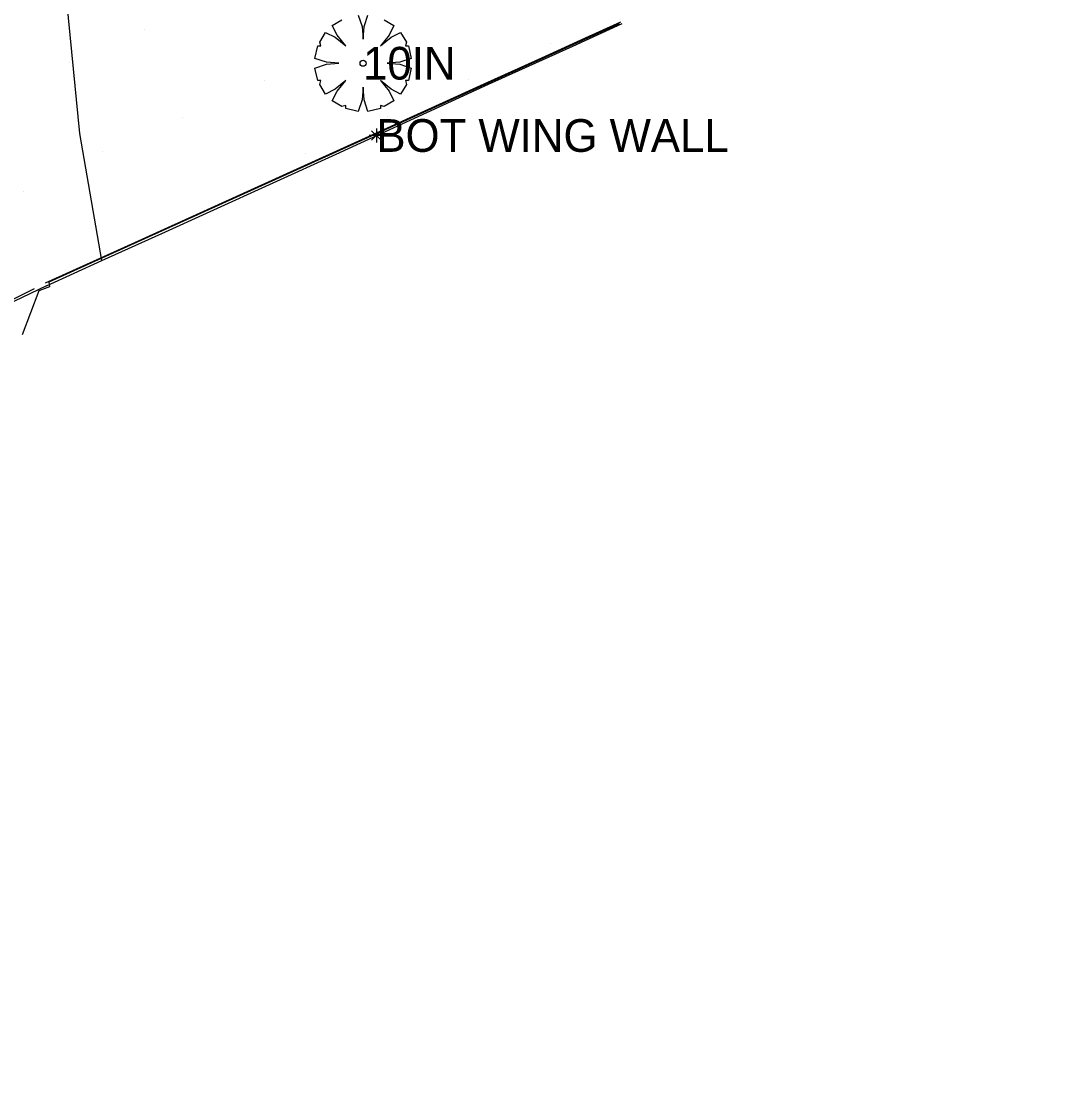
# Model space of a CAD drawing. Extents: x 1729983 to 1730242, y 468641 to 469019.
# Drawn here: x 1730180.1 to 1730237.3, y 468820 to 468879.2 of the extents above; entities that cross this region are included whole.
import ezdxf

# ---------------------------------------------------------------- set-up
doc = ezdxf.new("R2010")
doc.units = 0
for name, color, linetype in [('Default', 7, 'Continuous'), ('S_Bridge_Abutment_Bottom', 7, 'Continuous'), ('S_Bridge_Wingwall', 7, 'Continuous'), ('S_Ground_LevelString', 7, 'Continuous'), ('S_Ground_SpotElevation', 7, 'Continuous'), ('S_Misc_MiscFeature', 7, 'Continuous'), ('S_Misc_MiscItems', 7, 'Continuous'), ('S_Text', 7, 'Continuous'), ('S_Trees_Bush_Line', 7, 'Continuous'), ('S_Trees_Decid_NonPay', 7, 'Continuous')]:
    doc.layers.add(name, color=color, linetype=linetype)

# ---------------------------------------------------------------- blocks, each defined once
blk = doc.blocks.new('POINT_DISPLAY')
at = {"layer": 'Default'}
blk.add_line((0, 0), (0, 0), dxfattribs=at)

msp = doc.modelspace()

# ---------------------------------------------------------------- linework, layer by layer
at = {"layer": 'S_Bridge_Abutment_Bottom'}
msp.add_lwpolyline([(1730181.425, 468864.71), (1730176.506, 468862.351), (1730175.427, 468859.495), (1730170.121, 468844.945), (1730162.576, 468824.377), (1730156.015, 468806.678), (1730146.892, 468781.991), (1730136.8, 468754.596), (1730127.192, 468728.47), (1730129.433, 468723.646)], dxfattribs=at)
at = {"layer": 'S_Bridge_Wingwall'}
msp.add_line((1730212.958, 468879.124), (1730181.548, 468864.897), dxfattribs=at)
at = {"layer": 'S_Ground_LevelString'}
msp.add_lwpolyline([(1730181.376, 468864.866), (1730186.495, 468867.188), (1730190.484, 468868.996), (1730199.591, 468873.126), (1730205.729, 468875.909), (1730208.698, 468877.256), (1730211.096, 468878.343), (1730213.041, 468879.225)], dxfattribs=at)
at = {"layer": 'S_Misc_MiscFeature'}
for points in [[(1730181.425, 468864.71), (1730184.467, 468866.091), (1730187.769, 468867.579), (1730190.441, 468868.792), (1730197.367, 468871.957), (1730205.761, 468875.81), (1730210.394, 468877.895), (1730213.111, 468879.146)], [(1730181.548, 468864.897), (1730181.59, 468864.642), (1730181.002, 468864.425), (1730180.082, 468862.005)], [(1730180.75, 468864.535), (1730177.366, 468862.873), (1730174.461, 468854.957), (1730171.273, 468846.168), (1730167.811, 468836.657), (1730164.365, 468827.147), (1730154.502, 468800.309), (1730151.107, 468790.853), (1730144.524, 468772.905), (1730140.96, 468763.264), (1730137.54, 468754.064), (1730134.249, 468745.295), (1730130.903, 468736.495), (1730127.535, 468727.691), (1730129.089, 468724.341)]]:
    msp.add_lwpolyline(points, dxfattribs=at)
at = {"layer": 'S_Misc_MiscItems'}
for p, q in [((1730199.849, 468872.714), (1730199.325, 468873.238)), ((1730199.849, 468873.238), (1730199.325, 468872.714)), ((1730199.587, 468873.369), (1730199.587, 468872.583)), ((1730199.98, 468872.976), (1730199.194, 468872.976))]:
    msp.add_line(p, q, dxfattribs=at)
at = {"layer": 'S_Trees_Bush_Line'}
msp.add_lwpolyline([(1730184.467, 468866.091), (1730183.271, 468873.092), (1730182.282, 468883.021), (1730183.532, 468892.977), (1730185.386, 468899.513), (1730188.729, 468903.797), (1730194.277, 468909.059), (1730199.949, 468910.923), (1730207.487, 468909.415), (1730237.35, 468906.809)], dxfattribs=at)
at = {"layer": 'S_Trees_Decid_NonPay'}
for points in [[(1730198.589, 468879.606), (1730198.801, 468878.97), (1730198.854, 468878.28), (1730198.907, 468878.97), (1730199.119, 468879.606)], [(1730197.528, 468876.954), (1730196.839, 468877.007), (1730196.202, 468877.219), (1730196.361, 468877.909), (1730196.52, 468877.909), (1730196.467, 468878.121), (1730196.785, 468878.651), (1730197.315, 468878.386), (1730197.9, 468877.909), (1730197.422, 468878.492), (1730197.157, 468879.023), (1730197.687, 468879.341)], [(1730200.021, 468879.341), (1730200.552, 468879.023), (1730200.286, 468878.492), (1730199.809, 468877.909), (1730200.392, 468878.386), (1730200.922, 468878.651), (1730201.241, 468878.121), (1730201.188, 468877.909), (1730201.347, 468877.909), (1730201.507, 468877.219), (1730200.87, 468877.007), (1730200.18, 468876.954), (1730200.87, 468876.901), (1730201.507, 468876.689), (1730201.347, 468875.999), (1730201.188, 468875.999), (1730201.241, 468875.787), (1730200.922, 468875.257), (1730200.392, 468875.522), (1730199.809, 468875.999), (1730200.286, 468875.416), (1730200.552, 468874.885), (1730200.021, 468874.567), (1730199.809, 468874.62), (1730199.809, 468874.461), (1730199.119, 468874.302), (1730198.907, 468874.938), (1730198.854, 468875.628), (1730198.801, 468874.938), (1730198.589, 468874.302), (1730197.9, 468874.461), (1730197.9, 468874.62), (1730197.687, 468874.567), (1730197.157, 468874.885), (1730197.422, 468875.416), (1730197.9, 468875.999), (1730197.315, 468875.522), (1730196.785, 468875.257), (1730196.467, 468875.787), (1730196.52, 468875.999), (1730196.361, 468875.999), (1730196.202, 468876.689), (1730196.839, 468876.901), (1730197.528, 468876.954)]]:
    msp.add_lwpolyline(points, dxfattribs=at)
msp.add_circle((1730198.854, 468876.954), 0.166, dxfattribs=at)

# ---------------------------------------------------------------- block references
at = {"layer": 'S_Ground_SpotElevation'}
for p in [(1730186.798, 468878.791), (1730197.989, 468878.087), (1730209.161, 468878.028), (1730182.68, 468876.971), (1730193.408, 468875.995), (1730204.651, 468876.081), (1730188.91, 468873.953), (1730200.192, 468874.041), (1730184.517, 468872.07), (1730195.681, 468872.009), (1730180.159, 468869.918)]:
    msp.add_blockref('POINT_DISPLAY', p, dxfattribs=at)

# ---------------------------------------------------------------- texts
at = {"layer": 'S_Text'}
for s, p in [('10IN', (1730198.854, 468876.054)), ('BOT WING WALL', (1730199.587, 468872.076))]:
    msp.add_text(s, height=1.8, dxfattribs=at).set_placement(p)

doc.saveas('drawing.dxf')
